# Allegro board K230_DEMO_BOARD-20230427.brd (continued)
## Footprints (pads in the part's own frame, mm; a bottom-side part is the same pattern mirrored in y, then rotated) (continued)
HEAD2X8-100
  rect 1.524x1.524 hole 1.016: 1(0,0)
  round 1.524 hole 1.016: 2(0,2.54) 3(2.54,0) 4(2.54,2.54) 5(5.08,0) 6(5.08,2.54) 7(7.62,0) 8(7.62,2.54) 9(10.16,0) 10(10.16,2.54) 11(12.7,0) 12(12.7,2.54) 13(15.24,0) 14(15.24,2.54) 15(17.78,0) 16(17.78,2.54)
HEAD2X15-100
  rect 1.524x1.524 hole 1.016: 1(0,0)
  round 1.524 hole 1.016: 2(0,2.54) 3(2.54,0) 4(2.54,2.54) 5(5.08,0) 6(5.08,2.54) 7(7.62,0) 8(7.62,2.54) 9(10.16,0) 10(10.16,2.54) 11(12.7,0) 12(12.7,2.54) 13(15.24,0) 14(15.24,2.54) 15(17.78,0) 16(17.78,2.54) 17(20.32,0) 18(20.32,2.54) 19(22.86,0) 20(22.86,2.54) 21(25.4,0) 22(25.4,2.54) 23(27.94,0) 24(27.94,2.54) 25(30.48,0) 26(30.48,2.54) 27(33.02,0) 28(33.02,2.54) 29(35.56,0) 30(35.56,2.54)
HEAD6-100
  rect 1.524x1.524 hole 1.016: 1(0,0)
  round 1.524 hole 1.016: 2(2.54,0) 3(5.08,0) 4(7.62,0) 5(10.16,0) 6(12.7,0)
HEAD10-100
  rect 1.524x1.524 hole 1.016: 1(-7.62,0)
  round 1.524 hole 1.016: 2(-5.08,0) 3(-2.54,0) 4(0,0) 5(2.54,0) 6(5.08,0) 7(7.62,0) 8(10.16,0) 9(12.7,0) 10(15.24,0)
HEAD-100
  rect 1.524x1.524 hole 1.016: 1(0,0)
HOLE-M3
  round 5.969 hole 3.175: 1(0,0)
LED0603
  rect 0.762x0.813 smd: 1(-0.762,0) 2(0.762,0)
MIC4-028019-010
  rect 0.635x0.635 smd: 1(0.508,0.965) 2(0.508,-0.965) 3(-0.508,-0.965) 4(-0.508,0.965)
PL0404-028
  rect 1.524x4.064 smd: 1(1.4,0) 2(-1.4,0)
QFN8-050-0202-008-N
  rect 0.305x0.457 smd: 1(-0.75,-0.979) 2(-0.25,-0.979) 3(0.25,-0.979) 4(0.75,-0.979) 5(0.75,0.979) 6(0.25,0.979) 7(-0.25,0.979) 8(-0.75,0.979)
  rect 1.524x0.889 smd: 9(0,0)
QFN9-050-025015-010
  rect 0.254x0.559 smd: 1(-0.5,1.175) 4(-0.5,-1.175) 5(0,-1.175) 6(0.5,-1.175) 8(0.5,1.175) 9(0,1.175)
  rect 1.016x0.203 smd: 2(-0.475,0.4) 3(-0.475,-0.4) 7(0.475,0)
QFN12-040-018018-006
  rect 0.762x0.203 smd: 1(-0.9,0.2) 2(-0.9,-0.2) 7(0.9,-0.2) 8(0.9,0.2)
  rect 0.203x0.762 smd: 3(-0.6,-0.9) 4(-0.2,-0.9) 5(0.2,-0.9) 6(0.6,-0.9) 9(0.6,0.9) 10(0.2,0.9) 11(-0.2,0.9) 12(-0.6,0.9)
QFN64-050-0909-010-N
  oval 1.016x0.254 smd: 1(-4.55,3.75) 2(-4.55,3.25) 3(-4.55,2.75) 4(-4.55,2.25) 5(-4.55,1.75) 6(-4.55,1.25) 7(-4.55,0.75) 8(-4.55,0.25) 9(-4.55,-0.25) 10(-4.55,-0.75) 11(-4.55,-1.25) 12(-4.55,-1.75) 13(-4.55,-2.25) 14(-4.55,-2.75) 15(-4.55,-3.25) 16(-4.55,-3.75) 33(4.55,-3.75) 34(4.55,-3.25) 35(4.55,-2.75) 36(4.55,-2.25) 37(4.55,-1.75) 38(4.55,-1.25) 39(4.55,-0.75) 40(4.55,-0.25) 41(4.55,0.25) 42(4.55,0.75) 43(4.55,1.25) 44(4.55,1.75) 45(4.55,2.25) 46(4.55,2.75) 47(4.55,3.25) 48(4.55,3.75)
  oval 0.254x1.016 smd: 17(-3.75,-4.55) 18(-3.25,-4.55) 19(-2.75,-4.55) 20(-2.25,-4.55) 21(-1.75,-4.55) 22(-1.25,-4.55) 23(-0.75,-4.55) 24(-0.25,-4.55) 25(0.25,-4.55) 26(0.75,-4.55) 27(1.25,-4.55) 28(1.75,-4.55) 29(2.25,-4.55) 30(2.75,-4.55) 31(3.25,-4.55) 32(3.75,-4.55) 49(3.75,4.55) 50(3.25,4.55) 51(2.75,4.55) 52(2.25,4.55) 53(1.75,4.55) 54(1.25,4.55) 55(0.75,4.55) 56(0.25,4.55) 57(-0.25,4.55) 58(-0.75,4.55) 59(-1.25,4.55) 60(-1.75,4.55) 61(-2.25,4.55) 62(-2.75,4.55) 63(-3.25,4.55) 64(-3.75,4.55)
  rect 4.699x4.699 smd: 65(0,0)
R0402
  rect 0.635x0.508 smd: 1(-0.508,0) 2(0.508,0)
R0603
  rect 0.762x0.813 smd: 1(-0.762,0) 2(0.762,0)
R1206
  rect 1.397x1.651 smd: 1(-1.397,0) 2(1.397,0)
SOD523-2-28
  rect 0.508x0.406 smd: 1(-0.889,0) 2(0.889,0)
SOD523-2-28-H
  rect 0.508x0.406 smd: 1(-0.66,0) 2(0.66,0)
SOP16-75
  rect 2.032x1.016 smd: 1(-8.89,6.668) 2(-8.89,4.763) 3(-8.89,2.857) 4(-8.89,0.953) 5(-8.89,-0.953) 6(-8.89,-2.857) 7(-8.89,-4.763) 8(-8.89,-6.668) 9(8.89,-6.668) 10(8.89,-4.763) 11(8.89,-2.857) 12(8.89,-0.953) 13(8.89,0.953) 14(8.89,2.857) 15(8.89,4.763) 16(8.89,6.668)
SOT23-3-43
  rect 0.762x0.889 smd: 1(-0.95,-1.143) 2(0.95,-1.143) 3(0,1.143)
SOT23-5-36
  rect 0.635x1.016 smd: 1(-0.953,-1.295) 2(0,-1.295) 3(0.953,-1.295) 4(0.953,1.295) 5(-0.953,1.295)
SOT143-4-48
  rect 1.016x1.143 smd: 1(-0.747,-1.143)
  rect 0.635x1.143 smd: 2(0.953,-1.143) 3(0.953,1.143) 4(-0.953,1.143)
SW2-061036-025
  rect 2.032x1.016 smd: 1(3.016,0) 2(-3.016,0)
SW4-100-060050-035
  rect 1.016x2.159 smd: 1(-1.27,-4.386) 2(1.27,-4.386) 3(-1.27,4.386) 4(1.27,4.386)
TC1206
  rect 1.397x1.651 smd: 1(-1.397,0) 2(1.397,0)
TP28
  round 0.711 smd: 1(0,0)
TP40
  round 1.016 smd: 1(0,0)
TYPE-C-USB16-20-126-H-SMD-B
  round 0.711 hole 0.711 unplated: (-2.89,2.6) (2.89,2.6)
  rect 0.305x1.448 smd: A1(-3.375,3.974) A4(-2.6,3.974) A5(-1.25,3.974) A6(-0.25,3.974) A7(0.25,3.974) A8(1.25,3.974) A9(2.6,3.974) A12(3.375,3.974) B1(3.075,3.974) B4(2.3,3.974) B5(1.75,3.974) B6(0.75,3.974) B7(-0.75,3.974) B8(-1.75,3.974) B9(-2.3,3.974) B12(-3.075,3.974)
  oval 1.143x2.159 hole 0.762x1.778: P1(-4.32,3.13) P2(4.32,3.13)
  oval 1.143x1.651 hole 0.762x1.27: P3(-4.32,-1.05) P4(4.32,-1.05)
unnamed#2
  round 1.016 smd: 1(0,0)
unnamed#3
  round 5.08 hole 2.921: (-14,14) (-14,-14) (14,14) (14,-14)
  round 1.524 hole 1.524 unplated: (-10.5,10.5) (-10.5,-10.5) (10.5,10.5) (10.5,-10.5)
WSON8-065-0303-008-N
  rect 0.635x0.381 smd: 1(-1.41,0.975) 2(-1.41,0.325) 3(-1.41,-0.325) 4(-1.41,-0.975) 5(1.41,-0.975) 6(1.41,-0.325) 7(1.41,0.325) 8(1.41,0.975)
  rect 1.651x2.54 smd: 9(0,0)
X2-3215-008
  rect 1.016x1.778 smd: 1(-1.257,0) 2(1.257,0)
X4-2520-010
  rect 1.016x0.889 smd: 1(-0.914,-0.762) 2(0.914,-0.762) 3(0.914,0.762) 4(-0.914,0.762)
X4-3225-007
  rect 1.27x1.143 smd: 1(-1.1,-0.8) 2(1.1,-0.8) 3(1.1,0.8) 4(-1.1,0.8)
X4-3225-010
  rect 1.27x1.143 smd: 1(-1.1,-0.8) 2(1.1,-0.8) 3(1.1,0.8) 4(-1.1,0.8)

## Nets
AVDD_1V8: C14.1 C15.1 C151.1 R35.1 R164.2 TP9.1(TP) U1.F7(AVDD1P8_CODEC) U1.F8(AVDD1P8_ADC)
AVDD_PLL_0V8: C32.1 R154.2 TP20.1(TP) U1.G11(AVDD0P8_PLL)
AVSS1: C32.2 FB2.1 U1.F11(AVSS3)
GND: C1.2 C2.1 C3.2 C4.2 C5.2 C6.2 C7.2 C8.2 C9.2 C10.2 C11.2 C12.2 C13.1 C16.1 C17.2 C18.2 C19.2 C20.1 C21.2 C22.2 C23.1 C24.2 C25.2 C26.2 C27.2 C28.2 C29.2 C30.2 C31.2 C33.2 C34.2 C35.2 C36.2 C37.2 C38.2 C39.2 C40.2 C41.2 C42.2 C43.2 C44.2 C45.2 C46.2 C47.2 C48.2 C49.2 C50.2 C51.2 C52.2 C53.2 C54.2 C55.2 C56.2 C57.2 C58.2 C59.2 C60.2 C61.2 C63.2 C64.2 C65.2 C66.2 C67.2 C68.2 C69.2 C70.2 C71.2 C72.2 C73.2 C74.2 C75.2 C76.2 C77.2 C78.2 C79.2 C80.2 C81.2 C82.2 C83.2 C84.2 C85.2 C86.2 C87.2 C88.2 C89.2 C90.2 C92.1 C93.2 C94.2 C95.2 C96.2 C97.2 C98.2 C99.2 C100.2 C101.2 C102.2 C103.2 C104.2 C105.2 C106.2 C107.2 C108.2 C109.2 C110.2 C111.2 C112.2 C113.2 C114.2 C115.2 C116.2 C117.2 C118.2 C119.2 C120.2 C121.2 C122.2 C123.2 C124.2 C125.1 C126.2 C127.2 C128.1 C129.2 C130.2 C131.1 C132.1 C133.2 C134.2 C135.1 C136.1 C137.2 C138.1 C139.2 C140.2 C141.1 C142.2 C143.2 C144.1 C145.2 C146.2 C147.1 C148.2 C163.2 C164.2 C165.2 C166.1 C167.1 C168.2 C169.1 C171.2 C172.2 C173.2 C174.2 C175.1 C177.2 C178.2 C179.2 C180.2 C187.2 C188.2 C189.1 C191.2 C192.2 C193.2 C194.2 C195.1 C197.2 C198.2 C199.1 C200.1 C201.2 C202.1 C203.1 C204.2 C205.2 C206.1 C207.2 C208.1 C209.2 C210.2 C211.1 C212.2 C213.2 C214.2 C215.2 C216.1 C217.1 C218.1 C219.1 C220.1 C221.1 C222.1 C223.2 C224.2 C225.2 C226.2 C227.1 C228.2 C229.2 C230.1 C231.2 C232.2 C233.2 C234.2 C239.2 C240.2 C241.1 C242.1 C243.2 C244.1 C245.2 C246.2 C247.2 C248.2 C249.2 C250.2 C251.2 C252.2 C253.2 C254.2 C255.2 C256.2 C257.2 C258.2 C259.2 C260.2 C261.1 C262.2 C263.2 C265.1 C266.2 C267.2 C268.2 C269.2 C271.2 C272.1 C273.2 C274.1 D1.1(ANODE) FB1.2 FB2.2 J1.6 J1.12 J2.A1(GND0) J2.A12(GND1) J2.B1(GND3) J2.B12(GND2) J2.P1 J2.P2 J2.P3 J2.P4 J3.5 J3.6 J3.11 J3.12 J3.17 J3.18 J3.23 J3.24 J3.28 J3.29 J3.33 J3.37 J3.54 J3.55 J4.1 J4.2 J4.7 J4.12 J4.15 J4.18 J4.21 J4.24 J4.27 J4.30 J4.31 J4.32 J5.5 J5.11 J5.12 J6.A1(GND0) J6.A12(GND1) J6.B1(GND3) J6.B12(GND2) J6.P1 J6.P2 J6.P3 J6.P4 J8.10 J8.14 J9.2 J9.15 J10.17 J10.18 J10.27 J10.28 J11.A1(GND0) J11.A12(GND1) J11.B1(GND3) J11.B12(GND2) J11.P1 J11.P2 J11.P3 J11.P4 J12.2 J12.9 J12.10 J13.A1(GND0) J13.A12(GND1) J13.B1(GND3) J13.B12(GND2) J13.P1 J13.P2 J13.P3 J13.P4 K1.3 K1.4 K2.1 K3.3 LED1.2(ANODE) M1.1 M2.1 M3.1 M4.1 M5.1 M6.1 Q2.2(SOURCE) R9.2 R13.2 R14.2 R37.1 R40.1 R41.2 R42.2 R44.2 R45.1 R46.2 R56.1 R58.2 R61.2 R63.1 R67.2 R69.2 R70.1 R73.1 R75.1 R78.1 R82.1 R86.1 R90.1 R130.1 R132.1 R134.1 R140.2 R146.1 R157.2 R159.2 R163.2 R167.2 R170.1 R175.2 R176.2 R178.2 R187.2 R192.1 R195.2 R202.1 R211.2 R215.2 R244.2 R251.2 R252.1 R253.1 R255.1 R257.1 R259.1 R261.1 R266.1 TP3.1(TP) TP6.1(TP) TP8.1(TP) TP11.1(TP) TP13.1(TP) TP16.1(TP) TP19.1(TP) TP22.1(TP) TVS1.2(A2) TVS2.2(A2) TVS3.2(A2) TVS4.2(A2) TVS5.2(A2) TVS6.2(A2) TVS7.2(A2) TVS8.2(A2) TVS9.2(A2) TVS10.2(A2) TVS11.2(A2) TVS12.2(A2) U1.A13(VSS91) U1.A16(VSS90) U1.A19(VSS92) U1.B13(VSS93) U1.B20(VSS94) U1.C13(VSS95) U1.D9(VSS96) U1.D10(VSS99) U1.D11(VSS97) U1.D13(VSS98) U1.D15(VSS100) U1.E4(VSS75) U1.E6(VSS72) U1.E7(VSS73) U1.E8(VSS74) U1.E12(VSS78) U1.E13(VSS79) U1.E14(VSS80) U1.E15(VSS81) U1.E16(VSS82) U1.E19(VSS77) U1.F4(VSS53) U1.F6(VSS55) U1.F10(VSS76) U1.F16(VSS54) U1.G6(VSS89) U1.G13(VSS49) U1.G14(VSS50) U1.G15(VSS51) U1.G16(VSS52) U1.H7(VSS88) U1.H11(VSS83) U1.H13(VSS85) U1.H15(VSS86) U1.H16(VSS87) U1.H20(VSS84) U1.J7(VSS3) U1.J11(VSS1) U1.J13(VSS0) U1.J15(VSS2) U1.K3(VSS4) U1.K6(VSS7) U1.K8(VSS9) U1.K10(VSS10) U1.K12(VSS8) U1.K14(VSS6) U1.K16(VSS5) U1.K18(VSS56) U1.L7(VSS11) U1.L8(VSS12) U1.L10(VSS14) U1.L12(VSS16) U1.L15(VSS15) U1.L19(VSS13) U1.M6(VSS17) U1.M8(VSS19) U1.M10(VSS20) U1.M12(VSS18) U1.M15(VSS21) U1.M16(VSS22) U1.N3(VSS26) U1.N5(VSS24) U1.N8(VSS27) U1.N10(VSS23) U1.N12(VSS25) U1.N15(VSS28) U1.N16(VSS29) U1.P6(VSS30) U1.P7(VSS31) U1.P8(VSS32) U1.P10(VSS34) U1.P12(VSS33) U1.P14(VSS43) U1.P15(VSS44) U1.P20(VSS40) U1.R3(VSS36) U1.R6(VSS38) U1.R7(VSS39) U1.R10(VSS41) U1.R12(VSS42) U1.R14(VSS35) U1.R16(VSS37) U1.T3(VSS48) U1.T7(VSS45) U1.T8(VSS46) U1.T9(VSS47) U1.T15(VSS60) U1.U3(VSS59) U1.U8(VSS58) U1.U19(VSS57) U1.V3(VSS61) U1.V4(VSS62) U1.V5(VSS63) U1.V6(VSS64) U1.V7(VSS65) U1.V8(VSS66) U1.W1(VSS67) U1.W16(VSS68) U1.W20(VSS71) U1.Y13(VSS69) U1.Y19(VSS70) U2.3(GND) U2.7(POWERPAD) U3.2(GND) U4.6(VSS) U4.10(GND1) U4.11(GND2) U4.12(GND3) U4.13(GND4) U5.B2(VSS#B2) U5.B5(VSS#B5) U5.B6(VSSQ#B6) U5.B12(VSSQ#B12) U5.C3(VSSCA#C3) U5.C5(VSS#C5) U5.C6(VSSQ#C6) U5.D3(VSSCA#D3) U5.D12(VSSQ#D12) U5.E4(VSS#E4) U5.E5(VSS#E5) U5.E6(VSSQ#E6) U5.F4(VSSCA#F4) U5.F5(VSS#F5) U5.F6(VSSQ#F6) U5.F12(VSSQ#F12) U5.G3(VSSCA#G3) U5.G4(VSSCA#G4) U5.G6(VSSQ#G6) U5.G9(VSSQ#G9) U5.H2(VSS#H2) U5.H10(VSSQ#H10) U5.J4(VSSCA#J4) U5.J12(VSS#J12) U5.K2(VSS#K2) U5.K10(VSSQ#K10) U5.L6(VSS#L6) U5.L9(VSSQ#L9) U5.M4(VSSCA#M4) U5.M5(VSS#M5) U5.M6(VSSQ#M6) U5.M12(VSSQ#M12) U5.N4(VSS#N4) U5.N5(VSS#N5) U5.N6(VSSQ#N6) U5.P3(VSSCA#P3) U5.P12(VSSQ#P12) U5.R4(VSS#R4) U5.R5(VSS#R5) U5.R6(VSSQ#R6) U5.T2(VSS#T2) U5.T3(VSS#T3) U5.T4(VSS#T4) U5.T5(VSS#T5) U5.T6(VSSQ#T6) U5.T12(VSSQ#T12) U6.2(GND) U8.3(GND) U8.7(POWERPAD) U9.3(GND) U9.7(POWERPAD) U10.8(GND1) U10.9(GND2) U11.6(GND) U11.11(TP) U12.3(GND) U12.7(POWERPAD) U13.3(GND) U13.7(POWERPAD) U14.3(GND) U14.7(POWERPAD) U15.3(GND) U15.7(POWERPAD) U16.7(GND) U17.4(PGND1) U17.8(SGND) U17.9(PGND2) U18.4(GND1) U18.5(GND2) U20.4(PGND1) U20.8(SGND) U20.9(PGND2) U21.4(PGND1) U21.8(SGND) U21.9(PGND2) U22.1(GND) U23.1(GND) U24.1(GND) U25.7(GND) U26.1(GND#1) U26.5(GND#5) U26.10(AGND) U26.11(GND#11) U26.13(TEST) U26.15(GND#15) U26.25(GND#25) U26.35(GND#35) U26.47(GND#47) U26.51(GND#51) U26.65(PAD) U27.1(AGND) U27.2(PGND) U28.1(AGND) U28.2(PGND) U29.3(GND) U29.7(POWERPAD) U30.A6(VSS#A6) U30.C4(VSSQ#C4) U30.E7(VSS#E7) U30.G5(VSS#G5) U30.H10(VSS#H10) U30.J5(VSS#J5) U30.K8(VSS#K8) U30.N2(VSSQ#N2) U30.N5(VSSQ#N5) U30.P4(VSSQ#P4) U30.P6(VSSQ#P6) U31.1(GND) U32.1(GND) U33.1(GND) Y2.2(GND) Y3.2(GND#2) Y3.4(GND#4) Y4.2(GND) Y5.2(GND#2) Y5.4(GND#4)
GND_SIGNAL: C14.2 C15.2 C149.2 C150.2 C151.2 C152.2 C153.2 C154.2 C155.2 C156.2 C158.1 C160.1 C162.2 C238.2 FB1.1 J7.2 TVS13.2(A2) TVS14.2(A2) U1.G7(AVSS2) U1.G8(AVSS1) U7.2(GND1) U7.3(GND2)
VBUS: F1.1 J2.A4(VBUS0) J2.A9(VBUS1) J2.B4(VBUS3) J2.B9(VBUS2)
VDD_1V8: C10.1 C23.2 C26.1 C28.1 C29.1 C31.1 C78.1 C79.1 C80.1 C127.1 C132.2 C140.1 C166.2 C206.2 C207.1 C242.2 C255.1 C256.1 C257.1 C258.1 C259.1 FB5.2 J5.7 J5.9 J8.12 J9.1 J10.8 J12.1 R18.2 R20.2 R36.1 R48.2 R49.2 R59.2 R143.1 R148.2 R153.1 R158.1 R168.2 R197.1 R198.1 R199.1 R200.1 R206.1 R207.1 R209.1 R212.2 R234.1 R235.1 R236.1 R237.1 R238.1 R239.1 R240.1 R241.1 TP2.1(TP) U1.E11(VDD1P8#E11) U1.F13(VDD1P8#F13) U1.H6(VDDIO3P3_3) U1.R11(VDDIO3P3_2) U1.R13(VDDIO3P3_0) U1.R15(VDDIO3P3_5) U9.6(IN) U10.4(IN) U11.1(IN1) U11.2(IN2) U13.6(IN) U25.2(VCCA) U30.C6(VCCQ#C6) U30.M4(VCCQ#M4) U30.N4(VCCQ#N4) U30.P3(VCCQ#P3) U30.P5(VCCQ#P5) Y4.4(VCC)
VDD_3V3: C18.1 C19.1 C22.1 C30.1 C81.1 C82.1 C83.1 C124.1 C139.1 C143.1 C145.1 C146.1 C208.2 C243.1 C244.2 C260.1 C272.2 FB4.2 J3.57 J3.59 J4.5 J4.6 J5.13 J5.15 J8.16 J9.16 J10.21 R19.1 R23.2 R139.1 R156.1 R162.1 R166.1 R188.1 R189.1 R190.1 R191.1 R193.1 R194.1 R196.1 R210.2 R222.2 R242.1 R243.1 R245.2 R265.1 TP5.1(TP) U1.E10(VDD3P3_SD) U1.M7(VDDIO3P3_4) U4.4(VDD) U8.6(IN) U14.6(IN) U15.6(IN) U16.2(VCCA) U25.1(VCCB) U30.E6(VCC#E6) U30.F5(VCC#F5) U30.J10(VCC#J10) U30.K9(VCC#K9)
VDD_5V: C9.1 C12.1 C134.1 C137.1 C164.1 C165.1 C168.1 C169.2 C173.1 C174.1 C175.2 C187.1 C188.1 C189.2 C193.1 C194.1 C195.2 C209.1 C210.1 C211.2 C228.1 C229.1 C230.2 C247.1 C248.1 C249.1 C250.1 D1.2(CATHODE) F1.2 Q1.2(SOURCE) R137.2 R151.1 R172.1 R186.1 R246.1 R264.1 TP21.1(TP) U2.6(IN) U11.4(BIAS) U12.6(IN) U17.3(IN) U18.2(IN) U20.3(IN) U21.3(IN) U27.3(VIN) U28.3(VIN)
VDD_5V_O: C16.2 C20.2 J3.56 J3.58 J3.60 J4.3 J4.4 J5.14 J5.16 Q1.3(DRAIN) R39.2 R43.2 R264.2 TP24.1(TP) U3.5(IN) U6.5(IN)
VDD_CORE_0V8: C33.1 C34.1 C35.1 C36.1 C37.1 C38.1 C39.1 C40.1 C41.1 C42.1 C43.1 C44.1 C45.1 C46.1 C47.1 C48.1 C240.1 C251.1 J10.15 R218.2 TP14.1(TP) U1.F12(VDD0P8_CORE#F12) U1.G9(VDD0P8_CORE#G9) U1.G10(VDD0P8_CORE#G10) U1.K9(VDD0P8_CORE#K9) U1.K11(VDD0P8_CORE#K11) U1.L9(VDD0P8_CORE#L9) U1.L11(VDD0P8_CORE#L11) U1.M9(VDD0P8_CORE#M9) U1.M11(VDD0P8_CORE#M11) U1.N9(VDD0P8_CORE#N9) U1.N11(VDD0P8_CORE#N11) U1.P9(VDD0P8_CORE#P9) U1.P11(VDD0P8_CORE#P11) U1.P13(VDD0P8_CORE#P13)
VDD_CORE_SY: C190.2 C191.1 C192.1 J10.13 L9.2 R174.2 R218.1
VDD_CPU_0V8: C57.1 C58.1 C59.1 C60.1 C61.1 C234.1 C253.1 J10.4 R214.2 TP17.1(TP) U1.G12(VDD0P8_CPU#G12) U1.H12(VDD0P8_CPU#H12) U1.J12(VDD0P8_CPU#J12)
VDD_CPU_TI: C231.1 C232.1 C233.1 J10.2 L3.2 R214.1 U28.8(VOS)
VDD_IO1V8_SY: C170.2 C171.1 C172.1 J10.6 L6.2 R149.2 R212.1
VDD_IO3V3_SY: C196.2 C197.1 C198.1 J10.19 L10.2 R169.2 R210.1
VDD_KPU_0V8: C49.1 C50.1 C51.1 C52.1 C53.1 C54.1 C55.1 C56.1 C180.1 C215.1 C252.1 C254.1 J10.7 R60.2 R213.2 TP23.1(TP) U1.H8(VDD0P8_KPU#H8) U1.H9(VDD0P8_KPU#H9) U1.H10(VDD0P8_KPU#H10) U1.J8(VDD0P8_KPU#J8) U1.J9(VDD0P8_KPU#J9) U1.J10(VDD0P8_KPU#J10)
VDD_KPU_TI: C212.1 C213.1 C214.1 J10.5 L1.2 R60.1 U27.8(VOS)
3D_CTRL_IN: J3.49 R83.1
3D_CTRL_OUT1: J3.47 R85.1
3D_CTRL_OUT2: J3.46 R87.1
ADC_0: J15.1 R25.1 R51.1
ADC_1: J15.2 R26.1 R52.1
ADC_2: J3.52 J15.3 R27.1
ADC_3: J15.4 R28.1
ADC_4: J15.5 R29.1
ADC_5: J15.6 R30.1 R221.1
BOOT0: R18.1 SW1.1(A1) TVS4.1(A1) U1.C8(GPIO0)
BOOT1: R20.1 SW1.2(A2) TVS5.1(A1) U1.C9(GPIO1)
CC1: J2.A5(CC1) J2.B5(CC2) R9.1
CC_T: J6.A5(CC1) J6.B5(CC2) R195.1
DDR_1V8: C117.1 C118.1 C119.1 C120.1 C121.1 C122.1 C123.1 J10.3 R21.2 TP1.1(TP) U5.A3(VDD1#A3) U5.A4(VDD1#A4) U5.A5(VDD1#A5) U5.A6(VDD1#A6) U5.A10(VDD1#A10) U5.U3(VDD1#U3) U5.U4(VDD1#U4) U5.U5(VDD1#U5) U5.U6(VDD1#U6) U5.U10(VDD1#U10)
DDR_1V8_TI: C125.2 FB3.1 J10.1 R21.1 R138.2 U8.1(OUT)
DDR_CORE_0V8: C63.1 C64.1 C65.1 C66.1 C67.1 C68.1 C227.2 J10.25 R32.2 TP7.1(TP) U1.K13(VDD0P8_DDR_CORE#K13) U1.L13(VDD0P8_DDR_CORE#L13) U1.M13(VDD0P8_DDR_CORE#M13) U1.N13(VDD0P8_DDR_CORE#N13)
DDR_CORE_TI: C128.2 J10.23 R32.1 R177.1 U9.1(OUT)
DDR_VAA_1V8: C76.1 C77.1 C269.1 FB3.2 TP4.1(TP) U1.K15(VAA_DDR)
DDR_VDD2_1V2: C62.2 C69.1 C70.1 C71.1 C72.1 C73.1 C74.1 C75.1 C91.2 C93.1 C94.1 C95.1 C96.1 C97.1 C98.1 C99.1 C100.1 C101.1 C102.1 C103.1 C104.1 C105.1 C106.1 C107.1 C108.1 C109.1 C110.1 C111.1 C112.1 C113.1 C114.1 C115.1 C116.1 C241.2 C264.2 C267.1 J10.16 R24.2 R57.1 R66.2 R68.1 R71.1 R72.1 R74.1 R76.1 R80.1 R84.1 R88.1 R129.1 R131.1 R133.1 R141.1 R144.1 R145.2 R254.1 R256.1 R258.1 R260.1 TP10.1(TP) U1.H14(VDD1P1_DDR_IO#H14) U1.J14(VDD1P1_DDR_IO#J14) U1.L14(VDD1P1_DDR_IO#L14) U1.M14(VDD1P1_DDR_IO#M14) U1.N14(VDD1P1_DDR_IO#N14) U5.A8(VDD2#A8) U5.A9(VDD2#A9) U5.A11(VDDQ#A11) U5.C12(VDDQ#C12) U5.D4(VDD2#D4) U5.D5(VDD2#D5) U5.D6(VDD2#D6) U5.E8(VDDQ#E8) U5.E12(VDDQ#E12) U5.F2(VDDCA#F2) U5.G2(VDDCA#G2) U5.G5(VDD2#G5) U5.G12(VDDQ#G12) U5.H3(VDDCA#H3) U5.H5(VDD2#H5) U5.H6(VDD2#H6) U5.H8(VDDQ#H8) U5.H9(VDDQ#H9) U5.H11(VDDQ#H11) U5.H12(VDD2#H12) U5.J5(VDD2#J5) U5.J6(VDD2#J6) U5.J9(VDDQ#J9) U5.J10(VDDQ#J10) U5.K5(VDD2#K5) U5.K6(VDD2#K6) U5.K8(VDDQ#K8) U5.K11(VDDQ#K11) U5.K12(VDD2#K12) U5.L2(VDDCA#L2) U5.L5(VDD2#L5) U5.L12(VDDQ#L12) U5.M2(VDDCA#M2) U5.N8(VDDQ#N8) U5.N12(VDDQ#N12) U5.P4(VDD2#P4) U5.P5(VDD2#P5) U5.P6(VDD2#P6) U5.R12(VDDQ#R12) U5.U8(VDD2#U8) U5.U9(VDD2#U9) U5.U11(VDDQ#U11)
DDR_VDDQ_TI: C167.2 J10.14 R24.1 R38.1 U11.9(OUT1) U11.10(OUT2)
DDR_VREF: C62.1 C261.2 C262.1 R57.2 R58.1 U1.K17(DDR_VREF)
DEBUG_DM: J6.A7(DN1) J6.B7(DN2) U26.7(DM)
DEBUG_DP: J6.A6(DP1) J6.B6(DP2) U26.8(DP)
DL_M_CLK2: J3.31 R116.2
DL_M_CLK3: J3.35 R118.2
DP_M_CLK1: J3.26 R89.1
DP_RST: J3.44 R179.1
DP_STROBE: J3.50 R181.1
DP_VSYNC: J3.48 R180.1
EMMC_CLK: R50.1 U1.A5(MMC0_CLK)
EMMC_CMD: R48.1 U1.D6(MMC0_CMD) U30.M5(CMD)
EMMC_D0: U1.D5(MMC0_D0) U30.A3(DAT0)
EMMC_D1: U1.C5(MMC0_D1) U30.A4(DAT1)
EMMC_D2: U1.B5(MMC0_D2) U30.A5(DAT2)
EMMC_D3: U1.C6(MMC0_D3) U30.B2(DAT3)
EMMC_D4: U1.D7(MMC0_D4) U30.B3(DAT4)
EMMC_D5: U1.A7(MMC0_D5) U30.B4(DAT5)
EMMC_D6: U1.B7(MMC0_D6) U30.B5(DAT6)
EMMC_D7: U1.C7(MMC0_D7) U30.B6(DAT7)
EMMC_RST: C25.1 R49.1 U1.A6(MMC0_RST_N) U30.K5(R\E\S\E\T\)
EMMC_STROBE: R47.1 R59.1 U1.B6(MMC0_STROBE)
FT_12MHZ_IN: C201.1 U26.2(OSCI) Y5.3(IN)
FT_12MHZ_OUT: C204.1 U26.3(OSCO) Y5.1(OUT)
FTVCC_1V8: C199.2 C202.2 C220.2 C221.2 C222.2 U26.12(VCORE#12) U26.37(VCORE#37) U26.49(VREGOUT) U26.64(VCORE#64)
FTVCC_3V3: C200.2 C203.2 C216.2 C217.2 C218.2 C219.2 C271.1 FB7.1 FB8.1 R196.2 R201.1 R203.1 R204.1 R205.1 R267.2 U16.1(VCCB) U26.20(VCCIO#20) U26.31(VCCIO#31) U26.42(VCCIO#42) U26.50(VREGIN) U26.56(VCCIO#56)
GPIO9: R81.1 R184.2
GPIO26: J8.1 R91.1
GPIO27: J3.36 J8.2 R93.1
GPIO28: J3.42 J8.3 R95.1
GPIO29: J8.4 R97.1 R182.2
GPIO30: J8.5 R99.1 R183.2
GPIO31: J8.8 R101.1 R208.2
GPIO32: J8.6 R103.1
GPIO33: J8.7 R105.1
GPIO34: J8.9 R107.1
GPIO35: J8.11 R109.1
GPIO36: J8.13 R111.1
GPIO37: J8.15 R113.1
GPIO42: R100.2 R181.2
GPIO43: R102.2 R180.2 R232.2
GPIO46: R108.2 R179.2
GPIO47: J3.30 R110.2
GPIO48: J3.32 R112.2
GPIO49: J3.34 R114.2
GPIO52: J5.2 J5.4 R119.1 U16.6(A4)
GPIO53: J5.6 R55.2 R120.1 R194.2 TVS12.1(A1) U16.5(A3)
GPIO60_3V3: R127.1 R242.2 U25.12(B1)
GPIO61_3V3: R128.1 R243.2 U25.11(B2)
HP_INSERT_DET: C162.1 J7.6 R35.2 R221.2
HPOUTL: C159.1 U1.G1(LINEOUTP(L))
HPOUTR: C161.1 U1.G2(LINEOUTN)
HSY0: J3.51 R51.2 R53.1
I2C0_SCL_1V8: J3.38 R234.2 U25.3(A1)
I2C0_SDA_1V8: J3.40 R235.2 U25.4(A2)
I2C1_SCL: J3.43 R96.2 R219.1 R240.2
I2C1_SDA: J3.45 R98.2 R217.1 R241.2
I2C3_SCL: J3.41 R104.2 R239.2
I2C3_SDA: J3.39 R106.2 R238.2
I2C4_SCL: J4.8 R77.1 R233.1 R236.2
I2C4_SDA: J4.9 R79.1 R220.1 R237.2
JTAG_RST: J12.7 R206.2 U1.V14(GPIO6)
JTAG_TCK: J12.3 R197.2 U1.W15(GPIO2)
JTAG_TDI: J12.5 R199.2 U1.V15(GPIO3)
JTAG_TDO: J12.4 R198.2 U1.Y15(GPIO4)
JTAG_TMS: J12.6 R200.2 U1.U14(GPIO5)
LCD_EN: J4.29 R208.1
LCD_RST: J4.28 R184.1
LP3_CA0: R84.2 R86.2 U1.K20(DDR_CLK0N_CA0_NA) U5.R2(CA0)
LP3_CA1: R88.2 R90.2 U1.L20(DDR_CLK0_CA1_NA) U5.P2(CA1)
LP3_CA2: R129.2 R130.2 U1.M20(DDR_A3_CA2_NA) U5.N2(CA2)
LP3_CA3: R131.2 R132.2 U1.L17(DDR_A4_CA3_NA) U5.N3(CA3)
LP3_CA4: R133.2 R134.2 U1.M19(DDR_A5_CA4_CAA0) U5.M3(CA4)
LP3_CA5: R141.2 R253.2 U1.L16(DDR_A6_CA5_CAA1) U5.F3(CA5)
LP3_CA6: R254.2 R255.2 U1.N19(DDR_A8_CA6_CAA2) U5.E3(CA6)
LP3_CA7: R256.2 R257.2 U1.N20(DDR_A7_CA7_CAA3) U5.E2(CA7)
LP3_CA8: R258.2 R259.2 U1.M18(DDR_A11_CA8_CAA4) U5.D2(CA8)
LP3_CA9: R260.2 R261.2 U1.P19(DDR_A12_CA9_CAA5) U5.C2(CA9)
LP3_CKE0: R76.2 R78.2 U1.N17(DDR_CKE0_CKE0_CKEA0) U5.K3(CKE)
LP3_CLK_C: R72.2 R73.2 U1.R20(DDR_A14_CLKN_CLKAN) U5.J2(CK_C)
LP3_CLK_T: R70.2 R71.2 U1.R19(DDR_BA2_CLK_CLKA) U5.J3(CK_T)
LP3_CS0: R74.2 R75.2 U1.T20(DDR_CS0N_CS0_CSA0) U5.L3(CS_N)
LP3_DM0: U1.D18(DDR_DM2_DM0_DMIB1) U5.L8(DM0)
LP3_DM1: U1.P17(DDR_DM1_DM1_DMIA1) U5.G8(DM1)
LP3_DM2: U1.C15(DDR_DM3_DM2_DMIB0) U5.P8(DM2)
LP3_DM3: U1.V17(DDR_DM0_DM3_DMIA0) U5.D8(DM3)
LP3_DQ0: U1.C17(DDR_DQ16_DQ0_DQB15) U5.P9(DQ0)
LP3_DQ1: U1.D16(DDR_DQ17_DQ1_DQB14) U5.N9(DQ1)
LP3_DQ2: U1.D17(DDR_DQ18_DQ2_DQB13) U5.N10(DQ2)
LP3_DQ3: U1.C18(DDR_DQ19_DQ3_DQB12) U5.N11(DQ3)
LP3_DQ4: U1.E18(DDR_DQ20_DQ4_DQB11) U5.M8(DQ4)
LP3_DQ5: U1.E17(DDR_DQ21_DQ5_DQB10) U5.M9(DQ5)
LP3_DQ6: U1.B19(DDR_DQ22_DQ6_DQB9) U5.M10(DQ6)
LP3_DQ7: U1.C19(DDR_DQ23_DQ7_DQB8) U5.M11(DQ7)
LP3_DQ8: U1.R18(DDR_DQ10_DQ10_DQA10) U5.F11(DQ8)
LP3_DQ9: U1.P16(DDR_DQ14_DQ14_DQA14) U5.F10(DQ9)
LP3_DQ10: U1.R17(DDR_DQ8_DQ8_DQA8) U5.F9(DQ10)
LP3_DQ11: U1.W19(DDR_DQ12_DQ12_DQA12) U5.F8(DQ11)
LP3_DQ12: U1.T18(DDR_DQ9_DQ9_DQA9) U5.E11(DQ12)
LP3_DQ13: U1.U20(DDR_DQ11_DQ11_DQA11) U5.E10(DQ13)
LP3_DQ14: U1.U18(DDR_DQ13_DQ13_DQA13) U5.E9(DQ14)
LP3_DQ15: U1.T17(DDR_DQ15_DQ15_DQA15) U5.D9(DQ15)
LP3_DQ16: U1.C14(DDR_DQ24_DQ16_DQB0) U5.T8(DQ16)
LP3_DQ17: U1.B14(DDR_DQ26_DQ18_DQB2) U5.T9(DQ17)
LP3_DQ18: U1.C16(DDR_DQ30_DQ22_DQB6) U5.T10(DQ18)
LP3_DQ19: U1.A17(DDR_DQ28_DQ20_DQB4) U5.T11(DQ19)
LP3_DQ20: U1.D14(DDR_DQ25_DQ17_DQB1) U5.R8(DQ20)
LP3_DQ21: U1.A14(DDR_DQ27_DQ19_DQB3) U5.R9(DQ21)
LP3_DQ22: U1.B17(DDR_DQ31_DQ23_DQB7) U5.R10(DQ22)
LP3_DQ23: U1.B16(DDR_DQ29_DQ21_DQB5) U5.R11(DQ23)
LP3_DQ24: U1.W18(DDR_DQ3_DQ27_DQA4) U5.C11(DQ24)
LP3_DQ25: U1.V18(DDR_DQ2_DQ26_DQA5) U5.C10(DQ25)
LP3_DQ26: U1.V16(DDR_DQ5_DQ29_DQA2) U5.C9(DQ26)
LP3_DQ27: U1.Y16(DDR_DQ4_DQ28_DQA3) U5.C8(DQ27)
LP3_DQ28: U1.Y18(DDR_DQ1_DQ25_DQA6) U5.B11(DQ28)
LP3_DQ29: U1.U17(DDR_DQ0_DQ24_DQA7) U5.B10(DQ29)
LP3_DQ30: U1.T16(DDR_DQ6_DQ30_DQA1) U5.B9(DQ30)
LP3_DQ31: U1.U16(DDR_DQ7_DQ31_DQA0) U5.B8(DQ31)
LP3_DQS0_C: U1.A18(DDR_DQS2N_DQS0N_DQSB1N) U5.L11(DQS0_C)
LP3_DQS0_T: U1.B18(DDR_DQS2_DQS0_DQSB1) U5.L10(DQS0_T)
LP3_DQS1_C: U1.V19(DDR_DQS1N_DQS1N_DQSA1N) U5.G11(DQS1_C)
LP3_DQS1_T: U1.V20(DDR_DQS1_DQS1_DQSA1) U5.G10(DQS1_T)
LP3_DQS2_C: U1.A15(DDR_DQS3N_DQS2N_DQSB0N) U5.P11(DQS2_C)
LP3_DQS2_T: U1.B15(DDR_DQS3_DQS2_DQSB0) U5.P10(DQS2_T)
LP3_DQS3_C: U1.Y17(DDR_DQS0N_DQS3N_DQSA0N) U5.D11(DQS3_C)
LP3_DQS3_T: U1.W17(DDR_DQS0_DQS3_DQSA0) U5.D10(DQS3_T)
LP3_ODT: R64.1 R80.2 R82.2 U1.L18(DDR_NA_ODT_NA)
LP3_VREFCA: C264.1 C265.2 C266.1 R68.2 R69.1 U5.H4(VREF_CA)
LP3_VREFDQ: C91.1 C92.2 C263.1 R66.1 R67.1 U5.J11(VREF_DQ)
MICBIAS: C152.1 C153.1 FB6.1 R31.1 TVS13.1(A1) U1.E3(MIC_BIAS)
MICNL: C154.1 U1.E2(MICIN1N)
MICNR: C238.1 U1.F2(CODEC_MICNR)
MICPL: C157.1 U1.E1(MICIN1P(L))
MICPR: C270.2 U1.F1(CODEC_MICPR)
MIPI_0V8: C85.1 C86.1 C87.1 C246.1 J10.11 R135.2 TP18.1(TP) U1.N6(AVDD0P8_MIPI#N6) U1.R8(AVDD0P8_MIPI#R8)
MIPI_0V8_TI: C141.2 J10.9 R135.1 R136.1 U13.1(OUT)
MIPI_1V8: C88.1 C89.1 C90.1 C245.1 J10.22 R160.2 R223.2 TP12.1(TP) U1.N7(AVDD1P8_MIPI#N7) U1.R9(AVDD1P8_MIPI#R9)
MIPI_1V8_TI: C144.2 J10.20 R160.1 R161.2 U14.1(OUT)
MIPI_RX0_CLK_N: J3.1 U1.Y2(MIPI_RX0_CLK_N)
MIPI_RX0_CLK_P: J3.3 U1.W2(MIPI_RX0_CLK_P)
MIPI_RX0_D0_N: J3.4 U1.W3(MIPI_RX0_D0_N)
MIPI_RX0_D0_P: J3.2 U1.Y3(MIPI_RX0_D0_P)
MIPI_RX0_D1_N: J3.9 U1.V1(MIPI_RX0_D1_N)
MIPI_RX0_D1_P: J3.7 U1.V2(MIPI_RX0_D1_P)
MIPI_RX1_CLK_N: J3.14 U1.W5(MIPI_RX1_CLK_N)
MIPI_RX1_CLK_P: J3.16 U1.Y5(MIPI_RX1_CLK_P)
MIPI_RX1_D2_N: J3.10 U1.Y4(MIPI_RX1_D2_N)
MIPI_RX1_D2_P: J3.8 U1.W4(MIPI_RX1_D2_P)
MIPI_RX1_D3_N: J3.20 U1.W6(MIPI_RX1_D3_N)
MIPI_RX1_D3_P: J3.22 U1.Y6(MIPI_RX1_D3_P)
MIPI_RX2_CLK_N: J3.25 U1.R2(MIPI_RX2_CLK_N)
MIPI_RX2_CLK_P: J3.27 U1.R1(MIPI_RX2_CLK_P)
MIPI_RX2_D4_N: J3.21 U1.T1(MIPI_RX2_D4_N)
MIPI_RX2_D4_P: J3.19 U1.T2(MIPI_RX2_D4_P)
MIPI_RX2_D5_N: J3.13 U1.U2(MIPI_RX2_D5_N)
MIPI_RX2_D5_P: J3.15 U1.U1(MIPI_RX2_D5_P)
MIPI_TX0_CLK_N: J4.19 U1.W9(MIPI_TX0_CLK_N)
MIPI_TX0_CLK_P: J4.20 U1.Y9(MIPI_TX0_CLK_P)
MIPI_TX0_D0_N: J4.22 U1.Y10(MIPI_TX0_D0_N)
MIPI_TX0_D0_P: J4.23 U1.W10(MIPI_TX0_D0_P)
MIPI_TX0_D1_N: J4.16 U1.W11(MIPI_TX0_D1_N)
MIPI_TX0_D1_P: J4.17 U1.Y11(MIPI_TX0_D1_P)
MIPI_TX1_D2_N: J4.13 U1.Y8(MIPI_TX1_D2_N)
MIPI_TX1_D2_P: J4.14 U1.W8(MIPI_TX1_D2_P)
MIPI_TX1_D3_N: J4.25 U1.W7(MIPI_TX1_D3_N)
MIPI_TX1_D3_P: J4.26 U1.Y7(MIPI_TX1_D3_P)
MMC1_CLK: R122.1 R188.2 U4.5(CLK) U22.3(I/O_2)
MMC1_CMD: R121.1 R162.2 U4.3(CMD) U22.2(I/O_1)
MMC1_D0: R123.1 R189.2 U4.7(DAT0) U23.2(I/O_1)
MMC1_D1: R124.1 R190.2 U4.8(DAT1) U23.3(I/O_2)
MMC1_D2: R125.1 R191.2 U4.1(DAT2) U24.2(I/O_1)
MMC1_D3: R126.1 R193.2 U4.2(CD/DAT3) U24.3(I/O_2)
NC_NC: J12.8 R207.2
OSPI_CLK: J9.14 U1.K1(GPIO15)
OSPI_CS: J9.6 U1.J5(GPIO14)
OSPI_D0: J9.13 U1.K2(GPIO16)
OSPI_D1: J9.7 U1.K4(GPIO17)
OSPI_D2: J9.9 U1.K5(GPIO18)
OSPI_D3: J9.3 U1.L1(GPIO19)
OSPI_D4: J9.12 U1.L2(GPIO20)
OSPI_D5: J9.5 U1.L3(GPIO21)
OSPI_D6: J9.10 U1.L4(GPIO22)
OSPI_D7: J9.4 U1.L5(GPIO23)
OSPI_DQS: J9.11 U1.L6(GPIO24)
PG_CORE: R151.2 U17.7(EN) U20.2(PG) U21.7(EN)
PW_EN: C268.1 J1.14 J1.16 U12.4(EN) U18.1(EN) U20.7(EN) U27.4(EN) U28.4(EN)
PWIN_FLASH: C27.1 J9.8 U1.K7(VDDIO3P3_1)
RTC_1V8: C5.1 C6.1 C7.1 J1.4 J1.8 J1.10 J10.12 R62.2 R142.2 R150.2 R262.2 TP15.1(TP) U1.F14(AVDD1P8_LDO) U1.F15(AVDD1P8_RTC) Y2.4(VCC)
RTC_1V8_TI: C135.2 J10.10 R142.1 R185.2 U2.1(OUT)
RTC_CLK_IN: R6.2 R7.2 U1.B12(CLK32K768_XIN)
RTC_CLK_OUT: R5.1 U1.A12(CLK32K768_XOUT)
RTC_INT0: R1.1 TVS1.1(A1) U1.C10(INT0)
RTC_INT1: R2.1 TVS2.1(A1) U1.B10(INT1)
RTC_INT2: R3.1 TVS6.1(A1) U1.A10(INT2)
RTC_INT3: R4.1 TVS7.1(A1) U1.A11(INT3)
RTC_INT4: R12.1 TVS8.1(A1) U1.C12(INT4)
RTC_INT5: R15.1 TVS9.1(A1) U1.D12(INT5)
RTC_OUT0: R16.1 R62.1 TVS10.1(A1) U1.B11(OUT0)
RTC_OUT1: R22.1 U1.C11(OUT1)
SYS_CLK_IN: R10.2 R11.2 U1.B8(CLK24M_XIN)
SYS_CLK_OUT: R8.2 U1.A8(CLK24M_XOUT)
SYS_ON_OFF: C1.1 J1.2 K1.1
SYS_RST: C13.2 K2.2 R22.2 R223.1 TVS3.1(A1) U1.B9(RSTN)
SYS_SW: C2.2 K3.2 R17.1 TVS11.1(A1)
TEST_EN: R252.2 U1.A9(TEST_EN)
TOUCH_INT: J4.10 R182.1
TOUCH_RST: J4.11 R183.1
U_3V3: C274.2 R224.2 R267.1 U29.1(OUT)
U_5V: C273.1 J6.A4(VBUS0) J6.A9(VBUS1) J6.B4(VBUS3) J6.B9(VBUS2) U29.4(EN) U29.6(IN)
UART0_RXD: R54.2 R94.2 U25.6(A4)
UART0_RXD_3V3: U25.9(B4) U26.16(ADBUS0)
UART0_TXD: R53.2 R92.2 U25.5(A3)
UART0_TXD_3V3: U25.10(B3) U26.17(ADBUS1)
UART3_CTS_FT: U16.10(B3) U26.40(BDBUS2)
UART3_RTS_FT: U16.9(B4) U26.41(BDBUS3)
UART3_RXD: J5.8 R117.1 U16.3(A1)
UART3_RXD_FT: U16.12(B1) U26.38(BDBUS0)
UART3_TXD: J5.10 R115.1 U16.4(A2)
UART3_TXD_FT: U16.11(B2) U26.39(BDBUS1)
USB0_DN: J11.A7(DN1) J11.B7(DN2) U1.B2(USB0_DN) U32.3(I/O_2)
USB0_DP: J11.A6(DP1) J11.B6(DP2) U1.A2(USB0_DP) U32.2(I/O_1)
USB0_ID: J11.A5(CC1) J11.B5(CC2) U1.D3(USB0_ID) U33.3(I/O_2)
USB0_OTG_EN: J5.1 R41.1 U3.4(EN)
USB0_OTG_VBUS: C17.1 J11.A4(VBUS0) J11.A9(VBUS1) J11.B4(VBUS3) J11.B9(VBUS2) U3.1(OUT)
USB0_VBUS: R39.1 U1.C3(USB0_VBUS)
USB1_DN: J13.A7(DN1) J13.B7(DN2) U1.A4(USB1_DN) U31.3(I/O_2)
USB1_DP: J13.A6(DP1) J13.B6(DP2) U1.B4(USB1_DP) U31.2(I/O_1)
USB1_ID: J13.A5(CC1) J13.B5(CC2) U1.B3(USB1_ID) U33.2(I/O_1)
USB1_OTG_EN: J5.3 R46.1 U6.4(EN)
USB1_OTG_VBUS: C21.1 J13.A4(VBUS0) J13.A9(VBUS1) J13.B4(VBUS3) J13.B9(VBUS2) U6.1(OUT)
USB1_VBUS: R43.1 U1.A3(USB1_VBUS)
VCM: C149.1 C150.1 U1.F3(CODEC_VCM)
VSY0: J3.53 R52.2 R54.1
VTEST: U1.D8(ANA_TS_VTEST) V-TS.1
N20962765: R7.1 Y2.3(OUT)
N20962780: C3.1 R5.2 Y1.1
N20962782: C4.1 R6.1 Y1.2
N20963869: R13.1 SW1.3(B1)
N20963881: R14.1 SW1.4(B2)
N20968799: R61.1 U1.K19(DDR_ZN)
N20969144: R248.1 U1.T19(DDR_NA_CS1_CSA1)
N20969162: R249.1 U1.P18(DDR_CKE1_CKE1_CKEA1)
N20974230: R42.1 U1.D4(USB0_TXRTUNE)
N20974244: R44.1 U1.C4(USB1_TXRTUNE)
N20974837: R40.2 U3.3(ISET)
N20975021: R45.2 U6.3(ISET)
N20990697: R11.1 Y4.3(OUT)
N20990724: C11.1 R10.1 Y3.3(IN)
N20990759: C8.1 R8.1 Y3.1(OUT)
N21006529: R65.2 U1.U6(MIPI_ATB)
N21013358: R77.2 U1.W14(GPIO7)
N21013362: R79.2 U1.U12(GPIO8)
N21013366: R81.2 U1.T13(GPIO9)
N21013370: R83.2 U1.U13(GPIO10)
N21013374: R85.2 U1.Y14(GPIO11)
N21013378: R87.2 U1.V13(GPIO12)
N21013382: R89.2 U1.T12(GPIO13)
N21014154: R116.1 U1.T14(GPIO62)
N21014156: R118.1 U1.U15(GPIO63)
N21014379: R92.1 U1.J4(GPIO38)
N21014381: R94.1 U1.J3(GPIO39)
N21014383: R96.1 U1.J2(GPIO40)
N21014385: R98.1 U1.J1(GPIO41)
N21014387: R100.1 U1.H1(GPIO42)
N21014389: R102.1 U1.J6(GPIO43)
N21014391: R104.1 U1.H2(GPIO44)
N21014393: R106.1 U1.H3(GPIO45)
N21014395: R108.1 U1.H4(GPIO46)
N21014397: R110.1 U1.H5(GPIO47)
N21014399: R112.1 U1.G4(GPIO48)
N21014401: R114.1 U1.G5(GPIO49)
N21015109: R115.2 U1.M5(GPIO50)
N21015111: R117.2 U1.M4(GPIO51)
N21015121: R119.2 U1.M3(GPIO52)
N21015123: R120.2 U1.N4(GPIO53)
N21015125: R121.2 U1.M2(GPIO54)
N21015127: R122.2 U1.N2(GPIO55)
N21015129: R123.2 U1.P3(GPIO56)
N21015131: R124.2 U1.N1(GPIO57)
N21015133: R125.2 U1.P1(GPIO58)
N21015135: R126.2 U1.P2(GPIO59)
N21015137: R127.2 U1.P5(GPIO60)
N21015139: R128.2 U1.P4(GPIO61)
N21015638: R91.2 U1.U11(GPIO26)
N21015640: R93.2 U1.W13(GPIO27)
N21015650: R95.2 U1.V12(GPIO28)
N21015652: R97.2 U1.V11(GPIO29)
N21015654: R99.2 U1.V10(GPIO30)
N21015656: R101.2 U1.V9(GPIO31)
N21015658: R103.2 U1.U10(GPIO32)
N21015660: R105.2 U1.T11(GPIO33)
N21015662: R107.2 U1.U9(GPIO34)
N21015664: R109.2 U1.W12(GPIO35)
N21015666: R111.2 U1.T10(GPIO36)
N21015668: R113.2 U1.Y12(GPIO37)
N21032968: C133.1 U10.3(SS)
N21033005: C131.2 R145.1 R147.1 U10.5(OUT1) U10.6(OUT2)
N21033021: R146.2 R147.2 U10.7(FB)
N21033049: C126.1 R139.2 U8.4(EN)
N21033134: R138.1 R140.1 U8.2(FB)
N21033168: R148.1 U10.2(EN)
N21033227: C129.1 R143.2 U9.4(EN)
N21033259: R177.2 R178.1 U9.2(FB)
N21033332: C130.1 R246.2 U10.1(BIAS)
N21034668: C84.1 FB4.1 U1.E9(AVDD3P3_USB)
N21049023: C157.2 J7.1 R31.2
N21049035: C159.2 J7.4
N21049037: C161.2 J7.3
N21049039: J7.8 R33.2
N21049041: J7.7 R34.2
N21049043: C160.2 R34.1
N21049045: C158.2 R33.1
N21053090: C163.1 U11.7(SS)
N21064344: R36.2 U11.5(EN)
N21069878: R37.2 R38.2 U11.8(FB)
N21080670: R168.1 U11.3(PG)
N21090577: C205.1 FB5.1 U1.F9(AVDD1P8_USB)
N21116221: C170.1 R149.1 R170.2 U17.1(FB)
N21116429: L6.1 U17.6(LX)
N21117359: C190.1 R174.1 R176.1 U20.1(FB)
N21117469: L9.1 U20.6(LX)
N21117960: C196.1 R169.1 R192.2 U21.1(FB)
N21118160: L10.1 U21.6(LX)
N21119930: C138.2 R154.1 R155.1 U12.1(OUT)
N21119979: R155.2 R157.1 U12.2(FB)
N21124782: C142.1 R158.2 U13.4(EN)
N21124810: R136.2 R159.1 U13.2(FB)
N21124907: C136.2 R144.2 U14.4(EN)
N21124957: R161.1 R163.1 U14.2(FB)
N21125022: C147.2 R164.1 R165.2 U15.1(OUT)
N21125032: C148.1 R166.2 U15.4(EN)
N21125082: R165.1 R167.1 U15.2(FB)
N21140101: K1.2 R262.1
N21140162: J1.1 R1.2
N21140164: J1.3 R2.2
N21140180: J1.5 R3.2
N21140182: J1.7 R4.2
N21140355: K3.1 R150.1
N21156680: R153.2 U17.2(PG)
N21156730: R156.2 U21.2(PG)
N21166978: R186.2 U2.4(EN)
N21166999: R185.1 R187.1 U2.2(FB)
N21185456: C225.1 C226.1 FB7.2 U26.4(VPHY)
N21185461: C223.1 C224.1 FB8.2 U26.9(VPLL)
N21191941: R201.2 U26.14(RESET#)
N21191953: R202.2 U26.6(REF)
N21192465: R203.2 U26.63(EECS)
N21192467: R204.2 U26.62(EECLK)
N21192469: R205.2 U26.61(EEDATA)
N21250278: R209.2 U25.8(OE)
N21252465: R25.2 U1.C2(ADC_0)
N21252472: R26.2 U1.D2(ADC_1)
N21252475: R27.2 U1.B1(ADC_2)
N21252478: R28.2 U1.G3(ADC_3)
N21252481: R29.2 U1.C1(ADC_4)
N21252484: R30.2 U1.D1(ADC_5)
N21259407: J1.11 R15.2
N21259420: J1.9 R12.2
N21259441: J1.13 R16.2
N21259446: J1.15 R17.2
N21267992: R211.1 U27.9(VSET/VID/PG)
N21268003: L1.1 U27.7(SW)
N21270973: C176.2 C177.1 C178.1 C179.1 L2.2 R152.2 R213.1
N21271057: L2.1 U18.3(LX1) U18.6(LX2)
N21271073: C176.1 R152.1 R175.1 R229.1 U18.8(FB)
N21271180: R172.2 U18.7(PG)
N21272323: R215.1 U28.9(VSET/VID/PG)
N21272325: L3.1 U28.7(SW)
N21284521: C239.1 R171.1 R230.2
N21284561: R229.2 R230.1
N21284570: R171.2 R232.1
N21299161: R217.2 U27.5(SDA)
N21299164: R219.2 U27.6(SCL)
N21299301: R220.2 U28.5(SDA)
N21299304: R233.2 U28.6(SCL)
N21314838: J10.29 J10.30 R222.1
N21326640: R245.1 U22.4(VCC)
N21346225: GPIO25.1 U1.M1(GPIO25)
N21347019: LED1.1(CATHODE) R19.2
N21376209: R64.2 U5.J8(ODT)
N21376277: R63.2 U5.B3(ZQ)
N21377535: R47.2 U30.H5(DS)
N21379070: C24.1 U30.C2(VDDI)
N21380363: R250.1 U1.J16(DDR_RESET_N)
N21407823: R251.1 U5.R3(NC)
N21433380: R50.2 U30.M6(CLK)
N21453086: R55.1 U4.9(DET)
N21465198: R56.2 U1.U7(MIPI_REXT)
N21605373: Q2.1(GATE) R265.2 R266.2
N21605375: Q2.3(DRAIN) R137.1 R263.1
N21605461: Q1.1(GATE) R263.2
N21607257: C155.1 FB6.2 U7.1(VDD)
N21607310: C156.1 C270.1 TVS14.1(A1) U7.4(OUT)
N21610834: R23.1 U16.8(OE)
N21611781: R224.1 R244.1 U29.2(FB)

Pads without a net: ID1 1; ID2 1; ID3 1; ID4 1; ID5 1; ID6 1; J2 A6 A7 A8 B6 B7 B8; J6 A8 B8; J10 24 26; J11 A8 B8; J13 A8 B8; R65 1; R248 2; R249 2; R250 2; U1 A20 C20 D19 D20 E20 F17 F18 F19 F20 G17 G18 G19 G20 H17 H18 H19 J17 J18 J19 J20 M17 N18 Y1 Y20; U2 5; U5 A1 A2 A12 A13 B1 B4 B13 C4 K4 K9 L4 T1 T13 U1 U2 U12 U13; U8 5; U9 5; U12 5; U13 5; U14 5; U15 5; U17 5; U20 5; U21 5; U23 4; U24 4; U26 18 19 21 22 23 24 26 27 28 29 30 32 33 34 36 43 44 45 46 48 52 53 54 55 57 58 59 60; U29 5; U30 A1 A2 A7 A8 A9 A10 A11 A12 A13 A14 B1 B7 B8 B9 B10 B11 B12 B13 B14 C1 C3 C5 C7 C8 C9 C10 C11 C12 C13 C14 D1 D2 D3 D4 D12 D13 D14 E1 E2 E3 E5 E8 E9 E10 E12 E13 E14 F1 F2 F3 F10 F12 F13 F14 G1 G2 G3 G10 G12 G13 G14 H1 H2 H3 H12 H13 H14 J1 J2 J3 J12 J13 J14 K1 K2 K3 K6 K7 K10 K12 K13 K14 L1 L2 L3 L12 L13 L14 M1 M2 M3 M7 M8 M9 M10 M11 M12 M13 M14 N1 N3 N6 N7 N8 N9 N10 N11 N12 N13 N14 P1 P2 P7 P8 P9 P10 P11 P12 P13 P14; U31 4; U32 4; U33 4; Y2 1; Y4 1

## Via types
v1: diameter 0.559, hole 0.254, TOP to BOTTOM, 1136 vias
v2: diameter 0.356, hole 0.203, TOP to BOTTOM, 479 vias
v3: diameter 0.457, hole 0.203, TOP to BOTTOM, 118 vias

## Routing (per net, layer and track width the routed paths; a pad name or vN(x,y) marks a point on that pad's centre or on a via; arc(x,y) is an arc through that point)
AVDD_1V8: length 38.5
  TOP w0.254: v2(31.82,82.61) U1.F7 U1.F8
  TOP w0.381: 73.03,118.24 v1(73.03,117.35)
  BOTTOM w0.254: 32.64,84.71 32.38,84.45 C14.1 32.38,83.17 v2(31.82,82.61) ; C151.1 C15.1 34.92,85.72 34.8,85.6
  BOTTOM w0.508: 62.49,92.71 68.2,92.71 71.75,96.27 71.75,116.08 v1(73.03,117.35)
  vias: v1(55.37,82.68) v1(55.37,81.53) v1(59.94,92.71) v1(61.21,92.71)
AVDD_PLL_0V8: length 20.3
  TOP w0.254: U1.G11 v2(31.17,79.36)
  ART06 w0.305: v2(31.17,79.36) 31.84,79.36 32.28,79.8 32.71,79.8 32.96,79.55 39.65,79.55 40.11,79.1 40.67,79.1 43.21,76.56 45.49,76.56 47.12,74.93 v1(47.12,74.17)
  BOTTOM w0.254: v2(31.17,79.36) 31.67,78.87 C32.1
  vias: v1(45.09,58.42) v1(45.09,57.4)
AVSS1: length 0.5
  TOP w0.254: v2(31.83,80.01) 31.82,80.01 U1.F11
GND: length 354
  TOP w0.076: 45.72,115.53 v2(45.97,115.79) 45.73,116.03 44.91,116.03 U30.N2 44.91,115.53 45.72,115.53
  TOP w0.203: U30.E7 42.16,112.52 v2(42.41,112.77) 42.42,112.78 U30.G5 ; U5.F12 26.44,57.52 26.44,57.94 27.04,58.54 v2(27.6,58.54) ; U30.C4 43.18,111.26 v2(43.08,111.26) ; U30.A6 42.29,109.41 v2(42.29,109.22) ; v1(57.93,116.58) 58.11,116.76 U25.7 ; v2(42.16,116.71) 42.23,116.71 U30.P6 U30.N5 U30.P4 v2(43.66,116.7) ; U30.H10 41.4,113.28 41.78,113.67 v2(41.78,113.79) 41.78,114.16 U30.K8 ; U16.7 44.88,118.67 v1(44.45,118.24)
  TOP w0.254: U5.R5 32.8,52.06 v2(32.8,52.14) ; U1.G15 U1.H15 ; U1.G15 v2(31.17,77.41) U1.G14 ; U1.G15 v2(31.17,76.76) U1.G16 ; U1.E8 v2(32.47,81.96) 32.15,82.28 U1.E7 v2(32.47,82.61) 32.15,82.93 U1.E6 ; v2(29.22,79.36) U1.K12 28.81,79.12 28.34,79.12 U1.L12 ; v2(31.5,52.14) 31.17,51.81 U5.N5 ; v2(25,50.54) 25,50.46 U5.C3 ; U1.E13 v2(31.82,78.06) ; U5.G6 27.28,52.61 v2(27.6,52.94) ; v2(33.45,48.94) 33.45,49.01 U5.T2 ; U5.P12 32.38,57.9 32.38,58.13 v2(32.8,58.54) ; U1.M8 v2(27.93,81.96) U1.L8 ; U1.P12 v2(26.63,78.71) U1.N12 ; U1.V6 23.7,82.93 v2(23.38,82.61) U1.V7 ; U1.J13 v2(29.87,78.06) U1.H13 ; U5.R4 32.47,51.01 v2(32.8,51.34) ; U5.F5 26.63,51.81 v2(26.3,52.14) ; U1.U19 v2(24.03,74.16) ; U1.R14 v2(25.98,77.41) U1.P14 ; U1.F16 v2(31.82,76.11) U1.E16 ; U1.H20 v2(30.52,74.16) ; v2(31.5,50.54) 31.82,50.21 U5.P3 ; v2(30.85,52.94) 30.85,52.86 U5.M6 ; U26.51 57.96,105.01 ; U1.P10 v2(26.63,80.66) ; U1.F10 v2(31.17,80.66) ; U5.J12 29.08,57.85 29.08,58.07 v2(29.55,58.54) ; U1.K16 v2(29.22,76.11) ; U1.H7 v2(29.87,82.61) U1.J7 ; v2(27.6,48.94) 27.6,49.01 U5.H2 ; v2(30.2,52.94) 30.2,52.86 U5.L6 ; U1.M15 v2(27.93,76.76) U1.L15 ; U1.L7 v2(27.93,82.61) U1.M6 ; U26.1 65.86,104.73 v1(66.43,104.16) ; U1.R16 v2(25.33,76.76) U1.T15 ; R67.2 33.15,61.72 v2(33.02,61.85) ; U1.C13 v2(33.12,78.06) ; U5.D12 25.33,57.42 v2(25,57.74) ; U1.W1 v2(22.73,86.51) ; U1.M10 v2(27.28,80.66) ; v2(25.65,51.34) 25.65,51.41 U5.E5 ; U5.D3 25.65,49.81 v2(25.65,49.74) ; v2(27.6,50.54) 27.6,50.61 U5.G4 ; U5.C5 24.28,51.34 v2(23.7,51.34) ; U1.U3 v2(24.03,85.21) U1.V3 ; U30.J5 43.55,113.78 v2(43.68,113.65) ; v2(30.85,52.14) 30.85,52.06 U5.M5 ; U1.Y13 21.49,78.39 21.49,78.38 v2(21.46,78.38) ; U1.D9 32.95,80.84 32.95,80.48 U1.D10 v2(33.12,80.01) U1.D11 ; U5.K10 29.22,55.67 v2(29.55,55.34) 29.87,55.02 U5.L9 ; U5.E6 25.65,52.22 v2(25.65,52.14) ; U1.B13 U1.A13 v2(35.18,78.39) ; v2(26.95,55.34) 27.28,55.02 U5.G9 ; v2(30.85,51.34) 31.17,51.01 U5.N4 ; U1.K10 v2(28.58,80.66) ; v2(32.8,56.94) 33.12,57.27 U5.T12 ; U1.J15 U1.H16 v2(30.52,76.11) ; U5.M4 30.52,50.86 v2(30.2,50.54) ; U1.W16 v2(23.38,76.76) ; U1.T3 v2(25.33,85.21) U1.R3 ; v2(25.98,76.76) U1.P15 ; U5.F4 26.63,51.01 v2(26.3,51.34) ; U5.B2 24.35,49.01 v2(24.35,48.94) ; U5.C6 24.68,52.62 v2(24.35,52.94) 24.03,52.61 U5.B6 ; U1.V4 23.7,84.23 v2(23.38,83.91) U1.V5 ; U1.R12 v2(25.33,78.71) ; U26.10 64.25,109.23 ; C92.1 C263.2 27.81,61.59 v2(27.69,61.59) ; U1.W20 v2(23.05,73.28) ; U5.T5 33.45,51.41 v2(33.45,51.34) ; U1.K8 v2(29.22,81.31) ; U1.N10 26.95,80.33 v2(26.63,80.01) ; U26.25 60.46,111.91 ; v2(28.25,51.34) 28.57,51.01 U5.J4 ; U1.E4 32,84.09 31.65,84.09 U1.F4 v2(31.17,84.56) ; U1.R10 v2(25.33,80.66) U1.T9 ; U1.J11 v2(29.87,80.01) U1.H11 ; U1.V8 v2(23.38,81.96) ; v2(33.45,50.54) 33.45,50.61 U5.T4 ; U1.P6 U1.R6 v2(25.33,83.26) ; U26.15 64.19,111.73 ; v2(32.47,78.71) 32.15,79.03 U1.E12 ; v2(23.7,52.14) 23.7,52.06 U5.B5 ; U1.L19 v2(28.57,74.16) ; U1.P20 v2(26.63,73.51) ; U1.R7 v2(25.33,82.61) U1.T7 ; U1.A16 v2(35.39,76.44) ; U1.K3 v2(29.22,85.21) ; v2(26.3,52.94) 26.63,52.62 U5.F6 ; U1.B20 v2(34.42,73.51) ; U1.G13 v2(30.53,78.06) ; U1.P8 v2(26.63,81.96) ; v2(26.63,81.96) U1.P7 ; v2(26.63,81.96) U1.N8 ; U26.35 57.11,111.23 ; U1.K18 v2(29.22,74.81) ; U1.F6 31.38,83.06 30.97,83.06 U1.G6 v2(30.52,83.26) ; v2(31.5,52.94) 31.5,52.86 U5.N6 ; U5.E4 25.65,50.61 v2(25.65,50.54) ; U1.K6 v2(29.22,82.61) ; v2(33.45,49.74) 33.45,49.81 U5.T3 ; U26.11 64.25,109.73 ; U5.B12 23.7,57.67 v2(23.7,57.74) ; U1.E15 v2(32.47,76.76) U1.D15 ; U1.N5 v2(26.63,83.91) ; U1.M12 v2(27.28,78.71) ; U1.A19 v2(34.43,74.81) ; U1.Y19 21.97,74.06 21.97,73.53 v2(22.1,73.41) ; U1.N15 v2(26.63,76.76) U1.N16 ; U5.K2 29.22,49.41 v2(29.55,49.74) ; U5.R6 32.47,52.46 v2(32.15,52.14) ; U1.K14 v2(29.22,78.06) ; U1.T8 v2(24.68,81.96) U1.U8 ; U26.13 64.25,110.73 ; U5.G3 26.95,49.81 v2(26.95,49.74) ; U1.N3 v2(27.28,84.56) ; U1.E14 v2(32.47,78.06) U1.D13 ; U1.M16 v2(27.28,76.11) ; U5.H10 27.93,55.67 v2(27.6,55.34) ; U1.L10 v2(27.93,80.66) ; v2(33.45,52.94) 33.45,52.86 U5.T6 ; v2(31.5,58.54) 30.99,58.03 30.99,57.8 U5.M12 ; U1.E19 v2(32.47,74.16) ; U26.5 64.25,106.73 ; U26.47 v1(55.13,105.23)
  TOP w0.305: J3.29 v1(39.75,128.75) ; J3.28 v1(39.25,132.59) ; J3.54 45.76,132.74 v1(45.91,132.59) ; J4.1 6.72,88.91 v1(6.48,89.15) 6.73,89.41 J4.2 ; C136.1 v1(13.84,32.77) ; J4.12 v1(6.91,94.41) ; C271.2 v1(46.48,121.79) ; J3.23 v1(38.25,128.75) ; v1(6.48,91.91) J4.7 ; J3.12 v1(35.25,132.59) ; R192.1 v1(39.5,6.73) ; 43.31,122.56 v1(43.31,121.79) ; J3.24 v1(38.25,132.59) ; J4.27 v3(6.91,101.91) ; C208.1 v1(59.84,119.88) ; R170.1 v1(39.5,16.26) ; C207.2 56.41,120.39 v1(56.41,119.88) ; J3.5 v1(33.75,128.75) ; J4.21 v3(6.91,98.91) ; C42.2 43.56,77.72 ; J4.24 v3(6.91,100.41) ; J3.55 v3(46.26,128.93) ; J3.17 v1(36.75,128.75) ; J3.11 v1(35.25,128.75) ; J3.18 v1(36.75,132.59) ; J3.37 41.76,129.08 41.45,128.78 v1(40.76,128.78) J3.33 ; J3.6 v1(33.75,132.59) ; J4.30 v1(6.91,103.41) ; U11.6 29.96,32.6 ; J4.18 v3(6.91,97.41) ; R176.2 v1(47.24,46.23) ; J4.15 v1(6.91,95.91) ; C142.2 v1(13.84,20.32)
  TOP w0.381: v1(68.96,58.67) 69.34,58.29 U6.2 ; TVS5.2 v1(73.41,40.01) ; R90.1 R130.1 ; R130.1 R75.1 ; R130.1 v1(32.89,43.31) ; R251.2 v1(38.1,47.24) ; FB1.2 v1(57.66,134.75) ; v1(35.18,43.31) R134.1 R86.1 ; v1(69.6,100.97) 69.6,101.88 C204.2 ; R63.1 v1(18.29,50.55) ; U10.8 20.61,32.72 ; R69.2 v1(27.18,43.31) ; 65.41,101.35 65.41,101.87 C201.2 ; v1(49.4,85.22) R44.2 R42.2 ; C133.2 v1(21.72,26.16) ; C34.2 43.56,76.96 ; TP3.1 v1(13.84,13.34) ; U31.1 70.22,64.77 v1(71.12,64.77) ; U32.1 v1(70.41,75) ; v1(52.83,70.23) C239.2 ; v1(52.83,70.23) v1(52.83,68.07) 52.83,67.56 52.45,67.18 v1(50.16,67.18) C3.2 ; v1(52.83,70.23) 52.83,71.63 v1(52.7,71.75) v1(50.16,71.75) C4.2 ; C8.2 50.16,77.98 ; R157.2 v1(42.16,52.7) ; v1(64.03,84.99) U4.6 ; R78.1 R253.1 v1(24.89,43.31) ; C130.2 18.29,25.78 v1(18.16,25.65) ; R175.2 52.96,73.66 ; U15.3 62,96.79 ; R132.1 v1(37.47,43.31) ; R178.2 v1(13.84,53.98) ; C206.1 v1(7.11,53.21) ; U3.2 v1(68.96,68.45) ; K2.1 v1(77.47,54.23) ; R266.1 v1(60.96,23.68) ; C2.1 v1(70.48,37.44) ; R37.1 30.35,37.47 ; C11.2 v1(50.29,82.04) ; v1(22.61,43.31) R255.1 R257.1 ; TVS4.2 v1(73.41,42.55) ; R252.1 v1(48.39,76.83) ; C129.2 v1(13.84,45.85) ; R187.2 v1(42.16,37.34) ; v1(20.32,43.31) R261.1 R259.1 ; R195.2 v1(66.55,109.6) ; R159.2 v1(13.84,28.19) ; J9.15 30.8,105.35 v1(31.24,105.79) ; C163.2 v1(31.37,37.47) ; 72.26,33.66 v1(73.03,33.66) ; C164.2 30.48,24.77 ; U29.3 55.34,100.34 ; Q2.2 v1(64.45,22.67) ; R140.2 v1(35.18,37.34) ; J9.2 v1(30.8,119.95) ; 72.26,31.75 v1(73.03,31.75) ; U33.1 v1(70.36,77.98) ; C1.2 v1(71.25,24.13) ; C126.2 v1(35.18,29.59) ; R163.2 v1(13.84,40.51) ; LED1.2 v1(16.89,7.37) ; R146.1 v1(19.94,37.47)
  BOTTOM w0.203: 31.88,81.92 31.92,81.96 v2(32.47,81.96)
  BOTTOM w0.254: v2(30.52,76.11) 30.73,76.11 30.99,75.86 C262.2 C261.1 ; v2(41.02,109.22) 40.89,109.35 C256.2 ; v2(31.03,71.04) 30.99,71.01 R58.2 ; C265.1 28.19,47.88 v2(28.19,47.5) ; C74.2 29.16,76.17 v2(29.22,76.11) ; v2(29.22,78.06) 29.21,78.08 C68.2 ; C85.2 24.41,85.85 24.03,85.47 v2(24.03,85.21) ; v2(28.57,74.16) 28.46,74.04 27.94,74.04 ; v2(25.33,83.26) 24.89,83.69 C86.2 ; C258.2 42.04,112.39 v2(42.41,112.77) ; C79.2 C27.2 ; C79.2 C29.2 ; C79.2 29.21,91.69 v2(28.94,91.96) ; C45.2 C48.2 C35.2 37.55,81.53 v2(37.47,81.45) 37.38,81.53 C84.2 ; FB2.2 35.18,78.66 v2(35.18,78.39) ; v2(31.17,80.66) 30.99,80.85 C52.2 C56.2 ; v2(30.2,50.54) 30.19,50.55 C266.2 ; C28.2 C80.2 v2(21.46,78.38) C31.2 ; C53.2 C54.2 C55.2 v2(37.21,89.66) ; C82.2 C83.2 36.96,79.5 C78.2 37.97,79.12 v2(38.23,78.87) ; C88.2 v2(20.45,78.38) ; C257.2 v2(42.16,116.71) ; C71.2 C76.2 33.15,73.91 32.89,74.16 v2(32.47,74.16) ; C119.2 C114.2 32.97,56.77 v2(32.8,56.94) ; C81.2 C30.2 25.91,85.72 25.84,85.72 v2(25.33,85.21) 25.61,84.92 25.69,84.92 C87.2 ; C89.2 24.06,81.28 v2(23.38,81.96) 22.94,81.96 R56.1 ; v2(40.5,76.33) 40.37,76.2 C36.2 C43.2 C44.2 ; C26.2 23.43,76.71 v2(23.38,76.76) 23.17,76.96 C65.2 C66.2 ; C106.2 23.62,57.66 v2(23.7,57.74) ; C37.2 35.63,76.2 v2(35.39,76.44) 35.29,76.33 C6.2 ; C40.2 26.75,79.88 v2(26.63,80.01) ; C58.2 C61.2 ; C90.2 C47.2 ; v2(26.63,71.56) 27.62,71.56 R61.2 ; v2(45.97,115.79) 45.81,115.95 C25.2
  BOTTOM w0.305: C203.1 62.62,111.49 ; 63.76,106.19 C225.2 C226.2 ; C224.2 63.76,109.49 ; C216.1 58.43,105.43 ; C222.1 63.51,105.43 v1(63.63,105.56) ; C242.1 30.8,120.21 v1(30.8,119.95) ; C218.1 60.46,105.43 ; C220.1 55.2,105.23 v1(55.13,105.23) ; R202.1 63.76,107.34 ; C221.1 57.67,110.38 ; C202.1 C217.1 57.54,105.3 v1(57.79,105.56) ; C148.2 61.34,94.87 v1(61.59,94.87) ; C200.1 57.54,111.65 v1(57.79,111.4) ; C199.1 63.63,110.51 ; C10.2 v1(52.32,82.93) ; C223.2 v1(63.63,108.48) ; C219.1 57.67,107.84 ; C19.2 C22.2 43.15,111.25 43.15,111.26 v2(43.08,111.26)
  BOTTOM w0.381: R41.2 66.42,70.1 v1(66.29,70.23) ; v1(57.66,134.75) 60.52,137.6 74.46,137.6 M3.1 ; U24.1 v1(64.39,91.31) ; R244.2 v1(54.99,98.42) ; v1(64.01,87.63) 64.14,87.5 U22.1 ; C7.2 v1(50.93,72.64) ; TVS7.2 v1(61.59,7.75) ; v1(54.61,7.75) 54.61,8 TVS10.2 ; R9.2 v1(75.82,14.48) ; C18.2 41.15,116.33 ; R167.2 v1(64.9,95.63) ; v1(70.99,84.07) 71.39,84.07 TVS12.2 ; R45.1 R46.2 66.85,61.47 v1(66.77,61.55) ; C17.2 v1(69.98,66.04) ; 21.72,51.82 21.72,50.93 ; 21.72,51.82 v1(20.83,51.82) ; 21.72,51.82 21.72,52.7 ; C260.2 v1(31.24,105.79) ; TVS6.2 v1(64.14,7.75) ; R82.1 v3(37.34,54.23) ; TVS1.2 v1(69.6,8.64) ; TVS2.2 v1(66.55,7.75) ; v1(69.98,55.88) C21.2 C20.1 66.8,55.88 v1(66.55,56.13) ; 47.75,10.03 46.99,10.03 v1(46.74,9.78) ; C16.1 66.67,66.04 v1(66.55,66.17) ; R40.1 68.83,70.1 v1(68.96,70.23) ; R69.2 v1(27.18,43.31) ; U23.1 v1(64.01,83.69) ; TVS11.2 v1(50.16,7.62) ; v1(45.72,113.16) 45.47,112.9 C24.2 ; R70.1 v1(30.61,43.31) ; C13.1 v1(76.07,49.02) ; TVS8.2 v1(59.05,7.75) ; TVS3.2 v1(75.82,50.16) ; TVS9.2 v1(56.52,7.75) ; C259.2 v1(36.7,108.71)
  vias: v1(1.27,109.22) v1(1.27,106.68) v1(1.27,104.14) v1(1.4,130.43) v1(1.4,127.89) v1(1.4,125.35) v1(1.4,122.81) v1(1.4,120.27) v1(1.4,117.73) v1(4.66,85.22) v1(5.08,107.31) v1(5.85,85.34) v1(6.35,107.31) v1(6.35,106.05) v1(6.35,104.78) v1(6.73,86.23) v1(7.62,124.46) v1(7.62,119.38) v1(7.87,138.94) v1(10.16,136.53) v1(10.16,131.44) v1(10.41,138.94) v1(12.57,55.24) v1(12.57,53.98) v1(12.57,48.26) v1(12.57,35.18) v1(12.57,29.21) v1(12.57,28.19) v1(12.57,22.73) v1(12.95,138.94) v1(13.84,55.24) v1(13.84,29.21) v1(13.97,48.26) v1(13.97,35.18) v1(13.97,22.73) v1(15.11,56.52) v1(15.11,55.24) v1(15.24,136.53) v1(15.24,42.8) v1(15.24,41.78) v1(15.37,48.26) v1(15.37,35.18) v1(15.37,22.73) v1(15.49,138.94) v1(16.76,50.55) v1(16.76,49.4) v1(16.76,48.26) v1(16.76,47.12) v1(16.76,45.97) v1(16.76,37.47) v1(16.76,36.32) v1(16.76,35.18) v1(16.76,34.04) v1(16.76,32.89) v1(16.76,25.02) v1(16.76,23.88) v1(16.76,22.73) v1(16.76,21.59) v1(16.76,20.45) v1(16.76,18.67) v1(16.76,17.4) v1(16.76,16.13) v1(16.76,13.97) v1(16.76,12.7) v1(18.03,138.94) v1(18.03,21.59) v1(18.03,20.45) v1(18.03,18.67) v1(18.03,17.4) v1(18.03,16.13) v1(18.03,12.7) v1(18.16,51.94) v1(18.16,24.77) v1(18.16,23.5) v1(18.8,49.28) v1(19.18,51.94) v1(19.43,24.77) v1(19.43,23.5) v1(19.43,15.37) v1(19.43,14.1) v1(20.57,138.94) v1(20.7,24.77) v1(20.7,23.5) v1(20.7,15.37) v1(20.7,14.1) v1(20.83,53.09) v1(21.97,24.77) v1(21.97,23.5) v1(21.97,22.23) v1(21.97,15.37) v1(21.97,14.1) v1(21.97,12.83) v1(23.11,138.94) v1(23.24,24.77) v1(23.24,23.5) v1(23.24,22.23) v1(23.24,15.37) v1(23.24,14.1) v1(23.24,12.83) v1(24.13,118.75) v1(24.26,33.27) v1(24.26,32) v1(24.26,30.73) v1(24.26,29.46) v1(24.77,26.04) v1(24.77,24.77) v1(24.77,23.5) v1(24.77,15.37) v1(24.77,14.1) v1(25.65,138.94) v1(25.65,34.54) v1(25.65,33.27) v1(25.65,32) v1(25.65,30.73) v1(25.65,29.46) v1(26.04,26.04) v1(26.04,24.77) v1(26.04,23.5) v1(26.04,15.37) v1(26.04,14.1) v1(27.3,24.77) v1(27.3,23.5) v1(27.3,15.37) v1(27.3,14.1) v1(28.19,138.94) v1(28.57,24.77) v1(28.57,23.5) v1(28.57,15.37) v1(28.57,14.1) v1(29.84,24.77) v1(29.84,23.5) v1(29.84,15.37) v1(29.84,14.1) v1(31.11,24.77) v1(31.11,23.5) v1(31.11,15.37) v1(31.11,14.1) v1(31.37,38.48) v1(31.37,32) v1(32.38,38.48) v1(32.38,37.47) v1(32.38,33.27) v1(32.38,32) v1(32.38,24.77) v1(32.38,23.5) v1(32.38,15.37) v1(32.38,14.1) v1(33.4,38.48) v1(33.4,37.47) v1(33.4,33.27) v1(33.4,32) v1(33.66,24.77) v1(33.66,23.5) v1(33.66,15.37) v1(33.66,14.1) v1(34.92,24.77) v1(34.92,23.5) v1(34.92,22.23) v1(34.92,20.95) v1(34.92,19.68) v1(34.92,18.41) v1(34.92,15.37) v1(34.92,14.1) v1(34.92,12.7) v1(34.92,11.43) v1(34.92,10.16) v1(34.92,8.89) v1(35.31,32) v1(36.2,24.77) v1(36.2,23.5) v1(36.2,22.23) v1(36.2,15.37) v1(36.2,14.1) v1(36.2,12.7) v1(36.7,32) v1(37.47,24.77) v1(37.47,23.5) v1(37.47,22.23) v1(37.47,15.37) v1(37.47,14.1) v1(37.47,12.7) v1(37.59,125.22) v1(38.1,34.29) v1(38.1,33.15) v1(38.1,32) v1(38.1,30.86) v1(38.1,29.72) v1(38.73,26.29) v1(38.73,24.77) v1(38.73,23.5) v1(38.73,15.37) v1(38.73,14.1) v1(39.37,36.83) v1(39.37,35.56) v1(39.37,34.29) v1(39.37,33.15) v1(39.37,32) v1(39.37,30.86) v1(39.37,29.72) v1(39.37,28.7) v1(40.01,24.77) v1(40.01,23.5) v1(40.01,15.37) v1(40.01,14.1) v1(41.27,27.56) v1(41.27,26.29) v1(41.27,15.37) v1(42.29,47.24) v1(42.29,32) v1(42.55,27.56) v1(42.55,26.29) v1(42.55,25.02) v1(43.69,78.49) v1(43.69,47.24) v1(43.69,32) v1(43.81,84.84) v1(43.81,83.69) v1(43.94,27.56) v1(43.94,26.29) v1(43.94,25.02) v1(43.94,23.75) v1(43.94,22.48) v1(44.58,78.49) v1(44.58,77.22) v1(45.09,34.29) v1(45.09,33.02) v1(45.09,32) v1(45.09,30.86) v1(45.09,29.72) v1(45.21,49.4) v1(45.21,48.26) v1(45.21,47.24) v1(45.21,46.1) v1(45.21,44.96) v1(45.34,27.56) v1(45.34,26.29) v1(45.34,25.02) v1(45.34,23.75) v1(45.34,22.48) v1(46.48,110.11) v1(46.74,12.83) v1(46.74,11.81) v1(46.74,10.79) v1(46.74,8.76) v1(46.74,7.75) v1(46.86,33.53) v1(46.86,32.26) v1(46.86,30.61) v1(46.86,29.08) v1(46.86,27.56) v1(46.86,26.29) v1(46.86,25.02) v1(46.86,23.75) v1(46.86,22.48) v1(47.12,39.5) v1(47.12,38.48) v1(47.12,37.47) v1(47.12,36.2) v1(47.37,110.11) v1(48.13,32.26) v1(48.13,30.61) v1(48.13,29.08) v1(48.13,26.29) v1(48.13,25.02) v1(48.13,23.75) v1(48.13,22.48) v1(48.26,40.77) v1(49.4,32.26) v1(49.4,30.61) v1(49.4,29.08) v1(49.4,26.29) v1(49.4,25.02) v1(49.4,23.75) v1(49.4,22.48) v1(49.53,50.8) v1(50.67,26.29) v1(50.67,25.02) v1(50.67,23.75) v1(50.8,50.8) v1(50.93,77.22) v1(51.05,87.76) v1(51.94,26.29) v1(52.07,95.5) v1(52.07,94.23) v1(52.07,50.8) v1(52.07,7.75) v1(52.2,77.22) v1(52.58,87.76) v1(52.7,75.82) v1(52.7,74.55) v1(52.7,73.28) v1(53.34,50.8) v1(53.34,49.53) v1(53.34,48.26) v1(53.34,7.75) v1(53.47,95.5) v1(53.98,101.6) v1(54.1,82.04) v1(54.1,77.22) v1(54.36,87.76) v1(54.36,86.23) v1(54.36,84.84) v1(54.36,83.44) v1(54.36,79.76) v1(54.61,62.23) v1(54.61,60.96) v1(54.61,59.69) v1(54.61,58.42) v1(54.61,57.15) v1(54.61,55.88) v1(54.61,54.61) v1(54.61,53.34) v1(54.61,52.07) v1(54.61,50.8) v1(54.61,49.53) v1(54.61,48.26) v1(54.61,46.99) v1(54.61,45.72) v1(54.74,95.5) v1(54.99,100.97) v1(54.99,99.69) v1(55.75,12.06) v1(55.88,62.23) v1(55.88,60.96) v1(55.88,59.69) v1(55.88,58.42) v1(55.88,57.15) v1(55.88,55.88) v1(55.88,54.61) v1(55.88,53.34) v1(55.88,52.07) v1(55.88,50.8) v1(55.88,49.53) v1(55.88,48.26) v1(55.88,46.99) v1(55.88,45.72) v1(55.88,44.45) v1(56.01,101.6) v1(56.01,95.5) v1(57.02,60.96) v1(57.02,59.69) v1(57.02,58.42) v1(57.02,57.15) v1(57.02,55.88) v1(57.02,54.61) v1(57.02,53.34) v1(57.02,50.8) v1(57.02,49.53) v1(57.02,48.26) v1(57.02,46.99) v1(57.02,45.72) v1(57.02,12.06) v1(57.28,95.5) v1(57.28,94.23) v1(57.79,107.21) v1(58.29,60.45) v1(58.29,55.5) v1(58.29,54.23) v1(58.29,52.96) v1(58.29,49.53) v1(58.29,48.26) v1(58.29,46.99) v1(58.29,45.72) v1(58.29,44.45) v1(58.29,12.06) v1(59.44,111.4) v1(59.44,109.75) v1(59.44,108.48) v1(59.44,107.21) v1(59.44,105.56) v1(59.56,49.53) v1(59.56,48.26) v1(59.56,46.99) v1(59.56,45.72) v1(59.56,44.45) v1(60.33,75.44) v1(60.33,74.17) v1(60.33,72.9) v1(60.71,111.4) v1(60.71,109.75) v1(60.71,108.48) v1(60.71,107.21) v1(60.71,105.56) v1(60.83,49.53) v1(60.83,48.26) v1(60.83,46.99) v1(61.59,97.41) v1(61.59,96.14) v1(61.59,75.44) v1(61.59,74.17) v1(61.59,72.9) v1(61.59,71.63) v1(61.59,70.36) v1(61.59,12.06) v1(61.98,111.4) v1(61.98,109.75) v1(61.98,108.48) v1(61.98,107.21) v1(61.98,105.56) v1(62.1,49.53) v1(62.61,97.92) v1(62.74,82.17) v1(62.74,78.92) v1(62.74,77.85) v1(62.74,76.71) v1(62.87,75.44) v1(62.87,74.17) v1(62.87,72.9) v1(62.87,71.63) v1(62.87,70.36) v1(62.87,69.09) v1(62.87,67.82) v1(62.87,12.06) v1(63.51,111.4) v1(63.63,109.75) v1(63.63,107.21) v1(63.75,97.92) v1(63.88,81.15) v1(63.88,77.85) v1(63.88,76.71) v1(64.01,88.65) v1(64.01,85.98) v1(64.01,75.44) v1(64.01,74.17) v1(64.01,72.9) v1(64.01,71.63) v1(64.01,70.36) v1(64.01,69.09) v1(64.14,13.21) v1(64.14,12.06) v1(65.15,100.97) v1(65.15,98.17) v1(65.28,99.57) v1(65.41,13.21) v1(65.41,12.06) v1(65.66,96.39) v1(65.66,93.98) v1(66.17,74.38) v1(66.17,71.33) v1(66.67,98.17) v1(66.67,13.21) v1(66.67,12.06) v1(66.77,63.84) v1(66.8,60.07) v1(66.93,96.39) v1(66.93,93.98) v1(67.69,80.01) v1(68.07,98.17) v1(68.2,96.39) v1(68.2,93.98) v1(68.83,80.01) v1(69.6,99.57) v1(69.6,98.17) v1(73.91,86.23) v1(74.42,81.53) v1(74.49,97.41) v1(74.49,94.87) v1(75.31,88.9) v1(75.31,87.63) v1(75.31,86.23) v1(75.82,81.53) v1(75.89,97.41) v1(75.89,94.87) v1(77.16,97.41) v1(77.16,96.14) v1(77.16,94.87) v1(77.22,81.53) v1(77.22,80.26) v2(18.03,56.01) v2(19.68,75.95) v2(20.81,71.96) v2(21.84,57.4) v2(21.84,56.02) v2(21.84,53.72) v2(21.97,71.96) v2(22,54.89) v2(22.35,65.66) v2(22.35,64.9) v2(25.98,80.66) v2(26.17,47.54) v2(26.95,47.54) v2(29.2,72.81) v2(30.2,47.54) v2(30.85,47.54) v2(34.42,71.56) v2(35.05,56.77) v2(35.05,55.75) v2(35.05,54.95) v2(35.37,51.34) v2(35.37,49.74) v2(36.24,74.23) v2(37.13,77.11) v2(37.47,74.23) v2(38.86,55.63) v2(39.5,116.71) v2(40.77,116.71) v2(41.91,58.8) v2(44.45,61.34) v3(2.16,99.75) v3(2.16,93.68) v3(2.16,91.4) v3(3.25,98.04) v3(3.25,95.37) v3(3.76,89.69) v3(3.76,87.02) v3(9.86,83.57) v3(11.58,83.57) v3(11.81,86.19) v3(13.59,87.45) v3(13.61,83.57) v3(14.62,84.89) v3(19.18,53.98) v3(19.18,53.09) v3(20.64,32) v3(21.59,32.58) v3(21.59,31.43) v3(22.54,32) v3(27.75,46.1) v3(28.01,32) v3(28.96,32.58) v3(28.96,31.43) v3(29.91,32) v3(30.04,46.1) v3(33.03,64.4) v3(34.04,64.4) v3(44.2,69.58) v3(44.2,68.83) v3(45.07,69.18) v3(45.59,87.64) v3(45.59,86.01)
